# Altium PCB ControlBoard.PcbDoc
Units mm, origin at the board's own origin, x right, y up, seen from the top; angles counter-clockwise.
Board outline 49.91 x 49.78 mm, 2 copper layers (Top Layer, Bottom Layer), stack 0.325 mm thick; 61 components, 68 nets, 312 pads, 113 vias.
Unrouted connection lines stored in the file: 1.
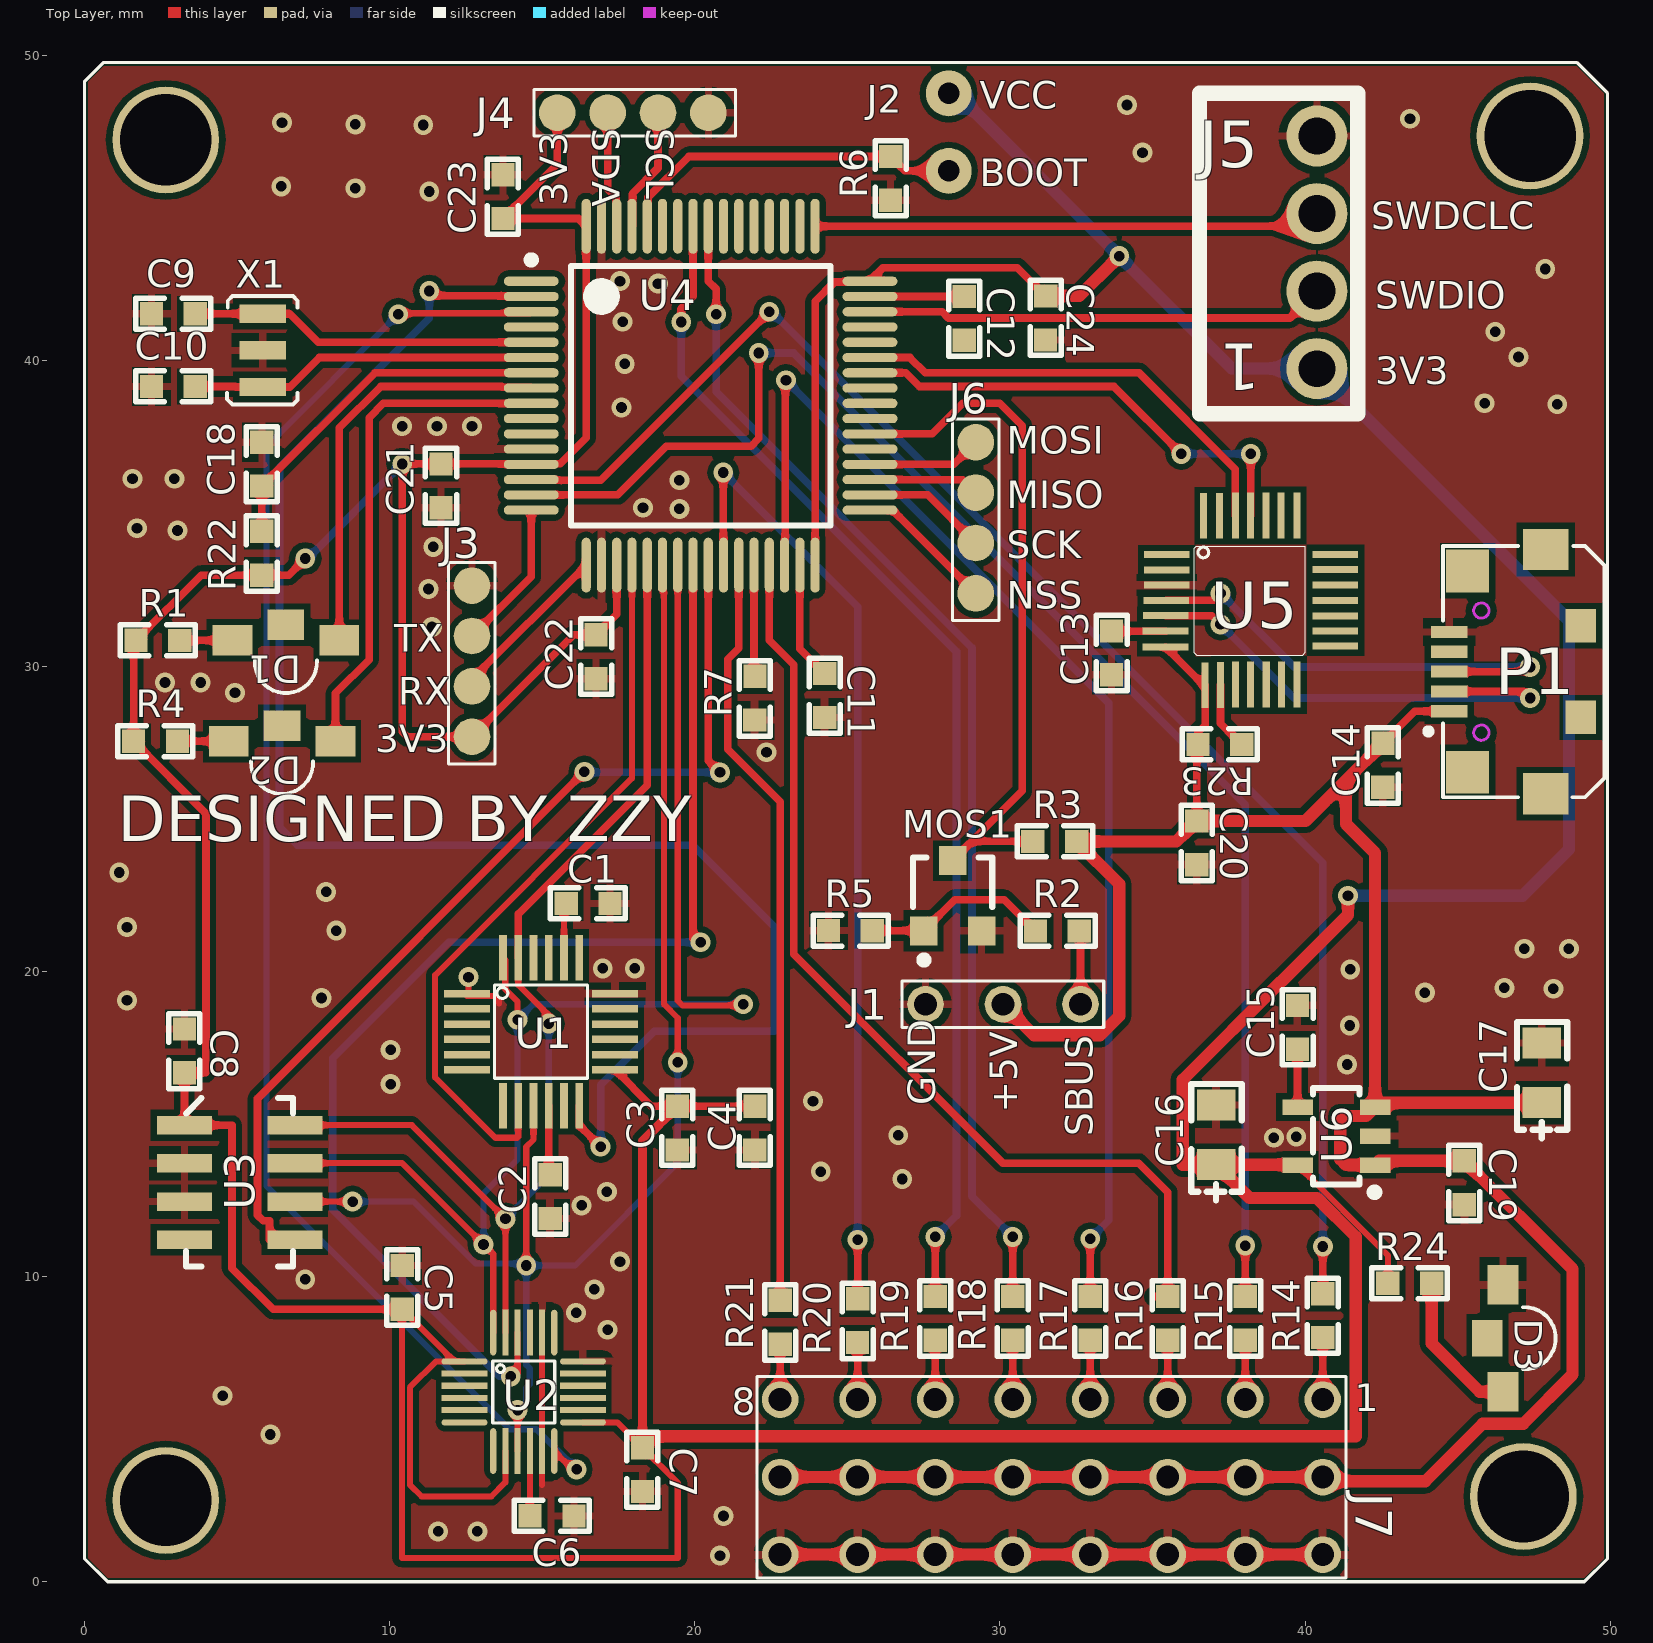
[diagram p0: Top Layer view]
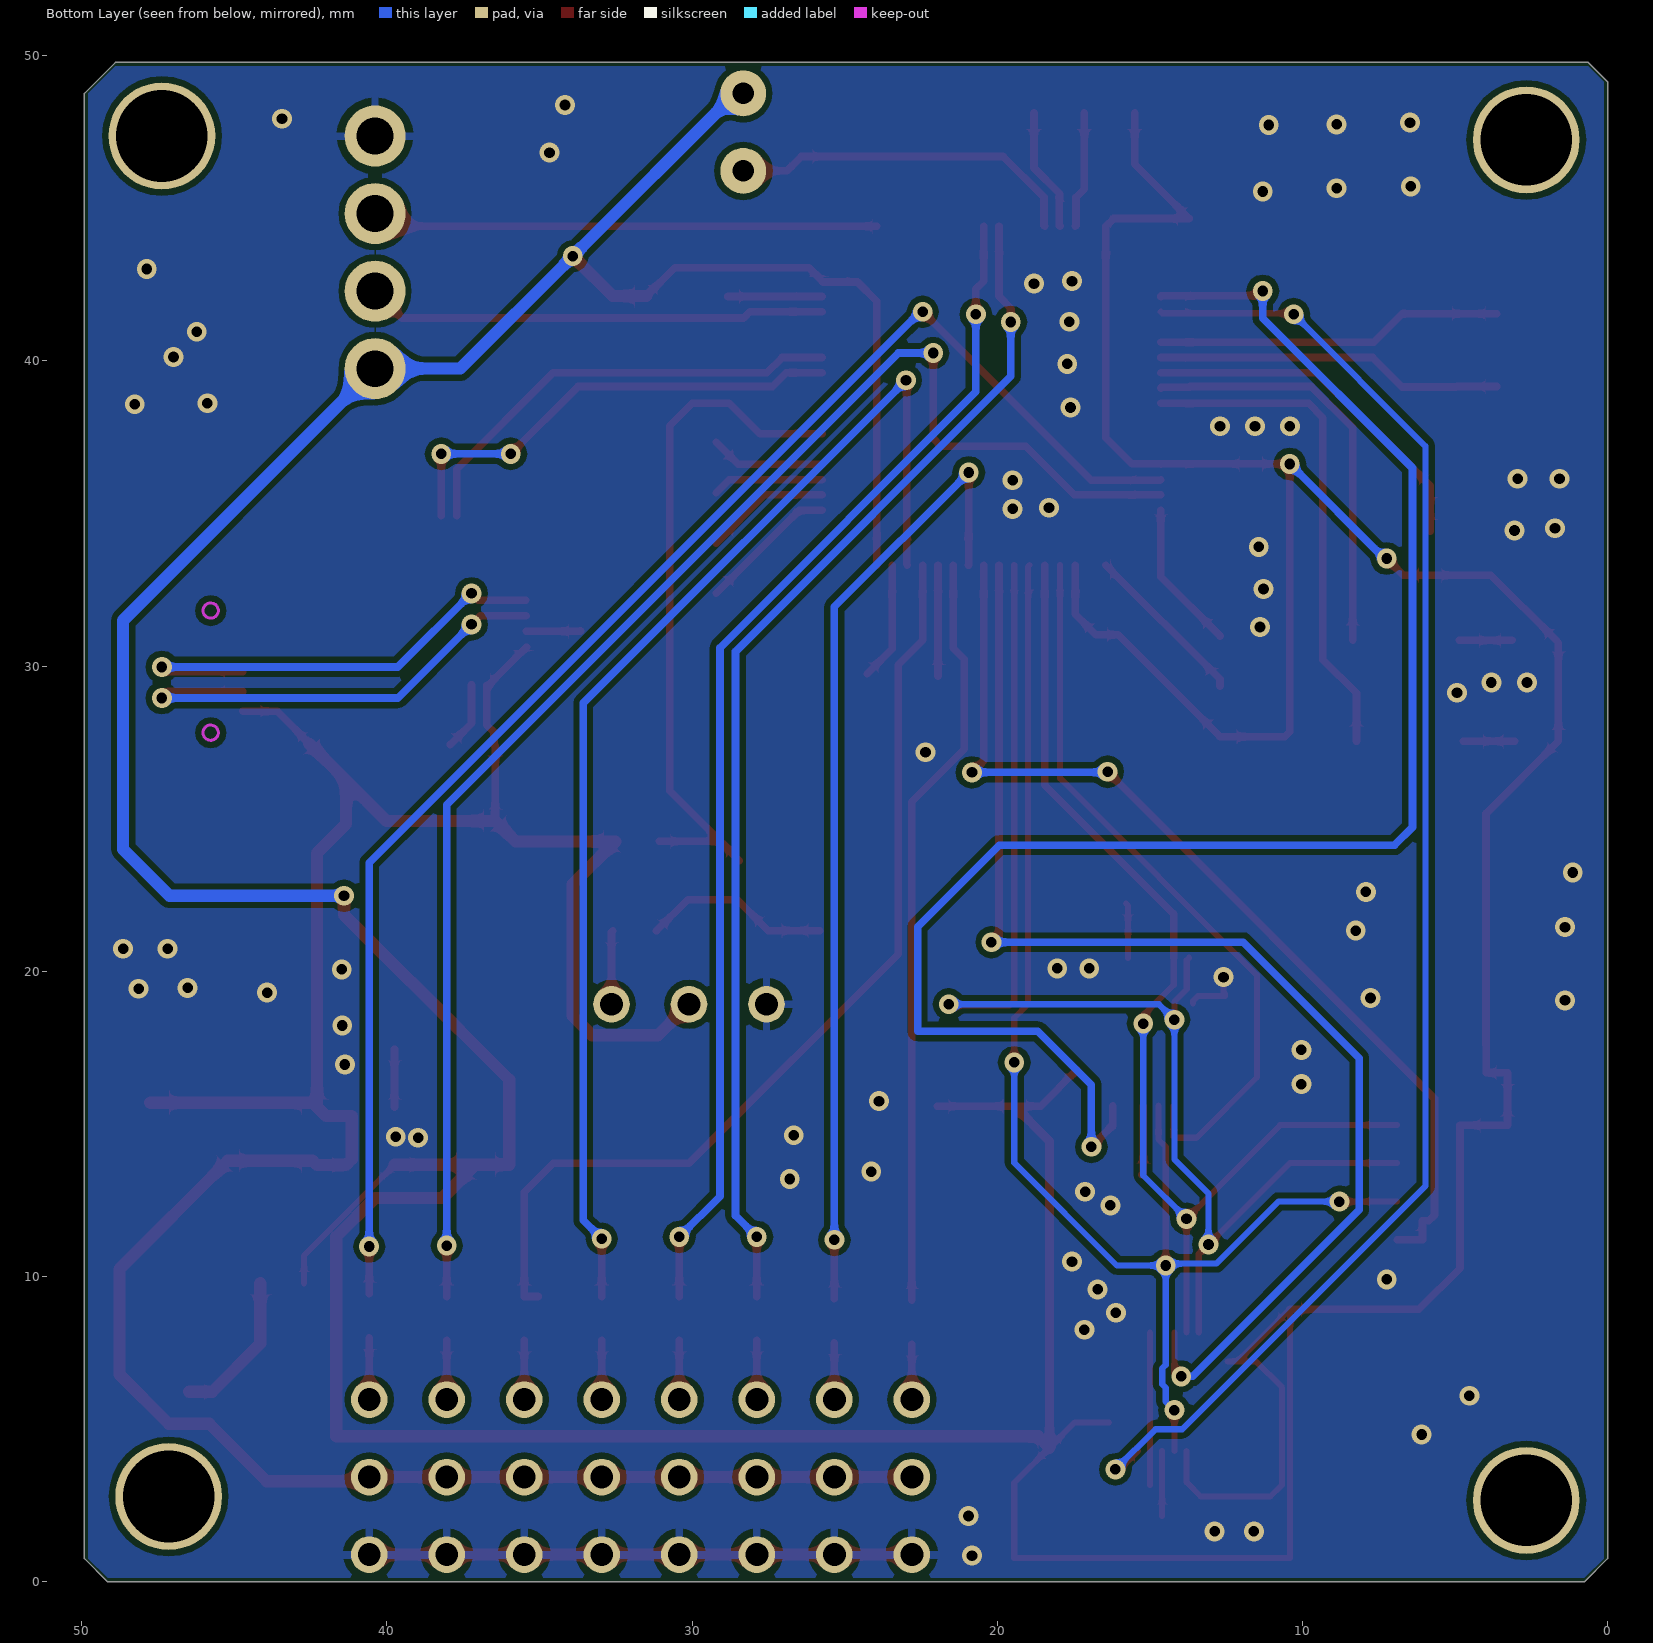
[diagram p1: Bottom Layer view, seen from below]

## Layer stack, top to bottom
Top Solder: solder mask 0.0102, Solder Resist, Dk 3.5
Top Layer: signal copper 0.0356
Dielectric 1: core 0.254, FR-4, Dk 4.2
Bottom Layer: signal copper 0.0356
Bottom Solder: solder mask 0.0102, Solder Resist, Dk 3.5

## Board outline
0,0.762 0,49.149 0.635,49.784 48.895,49.784 49.911,48.768 49.911,0.762 49.149,0 0.762,0

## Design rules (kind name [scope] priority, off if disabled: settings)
Clearance [All] p1: gap=0.2 ignorepadtopadclearanceinfootprint=FALSE except(0: Arc-Hole Track-Hole SMDPad-Hole THPad-Hole Via-Hole Fill-Hole Poly-Hole Region-Hole Text-Hole)
DiffPairsRouting [All] p1: maxlimit=0.254 minlimit=0.2 mostfreqgap=0.254 toplayer_minwidth=0.2 toplayer_maxwidth=0.381 toplayer_prefwidth=0.381 bottomlayer_minwidth=0.2 bottomlayer_maxwidth=0.381 bottomlayer_prefwidth=0.381 maxuncoupledlength=12.7
PolygonConnect [All] p1: connectstyle=Relief reliefconductorwidth=0.254 reliefentries=4 polygonreliefangle="90 Angle" airgapwidth=0.254
RoutingCorners [All] p1: cornerstyle=45-Degree minsetback=1.27 maxsetback=2.54
RoutingVias [All] p1: holewidth=0.35 width=0.65 viastyle="Through Hole" minholewidth=0.3 minwidth=0.6 maxholewidth=2 maxwidth=2
SolderMaskExpansion [All] p1: expansion=0.102
UnRoutedNet [All] p1: checkbadconnections=TRUE
Width [All] p1: maxlimit=2 minlimit=0.2 preferedwidth=0.3 minimp=50.000000 maximp=50.000000 favimp=50.000000
27 further rules are at their usual default settings.

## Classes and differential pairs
component class mcu: C9 C10 C11 C12 C13 C14 C15 C16 C17 C18 C19 C20 C21 C22 C23 C24 D1 D2 D3 J1 J2 J3 J4 J5 J6 J7 MOS1 P1 R1 R2 R3 R4 R5 R6 R7 R14 R15 R16 R17 R18 R19 R20 R21 R22 R23 R24 U4 U5 U6 X1
component class imu: C1 C2 C3 C4 C5 C6 C7 C8 U1 U2 U3

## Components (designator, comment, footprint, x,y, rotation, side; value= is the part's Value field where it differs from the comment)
C1 "0.01uF" 0603P 16.51,22.225 r180 top
C2 "2.2uF" 0603P 15.266,12.611 r90 top
C3 "2.2uF" 0603P 19.429,14.859 r90 top
C4 "0.1uF" 0603P 21.969,14.859 r90 top
C5 "0.1uF" 0603P 10.414,9.652 r270 top
C6 "0.1uF" 0603P 15.329,2.157 r180 top
C7 "0.01uF" 0603P 18.288,3.683 r270 top
C8 "0.1uF" 0603P 3.28,17.399 r270 top
C9 "22pF" 0603P 2.921,41.546 r180 top
C10 "22pF" 0603P 2.921,39.163 r180 top
C11 "2.2uF" 0603P 24.259,29.045 r270 top
C12 "2.2uF" 0603P 28.829,41.401 r270 top
C13 "0.1uF" 0603P 33.657,30.442 r270 top
C14 "0.1uF" 0603P 42.547,26.759 r270 top
C15 "104" 0603P 39.751,18.161 r90 top
C16 "10uF" "C0805 钽电容" 37.082,13.665 r90 top
C17 "100uF" "C0805 钽电容" 47.75,15.697 r90 top
C18 "104" 0603P 5.817,36.627 r270 top
C19 "104" 0603P 45.212,13.081 r270 top
C20 "1uF" 0603P 36.451,24.219 r270 top
C21 "0.1uF" 0603P 11.684,35.903 r90 top
C22 "0.1uF" 0603P 16.764,30.302 r90 top
C23 "0.1uF" 0603P 13.716,45.39 r270 top
C24 "0.1uF" 0603P 31.496,41.402 r90 top
D1 "LED" "LED1206  侧贴" 6.604,30.844 r180 top
D2 "LED" "LED1206  侧贴" 6.477,27.542 r180 top
D3 "LED" "LED1206  侧贴" 46.482,7.978 r270 top
J1 "SBUS" 3P 27.559,18.923 r90 top
J2 "BOOT" X3 28.321,48.768 r0 top
J3 "UART" 4P 12.7,32.639 r0 top
J4 "I2C" 4P 15.494,48.133 r90 top
J5 "SWD" X4 40.386,39.751 r180 top
J6 "SPI" 4P 29.21,37.338 r0 top
J7 "pwm" 3x8P 40.577,3.429 r270 top
MOS1 "SI2302" SO-G3/C2.5 28.448,22.479 r0 top
P1 "MICRO-USB" MICRO_USB5P_SOP 44.722,29.821 r270 top
R1 "510R" 0603P 2.413,30.844 r180 top
R2 "10K" 0603P 31.877,21.325 r0 top
R3 "10K" 0603P 31.788,24.259 r0 top
R4 "510R" 0603P 2.337,27.542 r180 top
R5 "10K" 0603P 25.095,21.336 r0 top
R6 "10K" 0603P 26.416,45.974 r90 top
R7 "10K" 0603P 21.971,28.956 r270 top
R14 "10K" 0603P 40.579,8.725 r270 top
R15 "10K" 0603P 38.037,8.636 r270 top
R16 "10K" 0603P 35.499,8.636 r270 top
R17 "10K" 0603P 32.957,8.636 r270 top
R18 "10K" 0603P 30.417,8.636 r270 top
R19 "10K" 0603P 27.879,8.636 r270 top
R20 "10K" 0603P 25.337,8.56 r270 top
R21 "10K" 0603P 22.799,8.509 r270 top
R22 "100K" 0603P 5.817,33.706 r270 top
R23 "10K" 0603P 37.211,27.432 r180 top
R24 "510R" 0603P 43.434,9.779 r180 top
U1 "mpu6000" MPU6050 14.966,18.022 r0 top
U2 "mpu9250" mpu9250 14.397,6.223 r0 top
U3 "MS5611-01BA" MS5611-01BA 5.08,13.081 r0 top value=10-1200mbar
U4 "STM32F405RGT6" STM-LQFP64_N 20.193,38.862 r0 top
U5 "CP2102" CP2102 38.225,32.155 r270 top
U6 "SP6205EM5-3.3" SOT23-5S 42.291,13.655 r180 top
X1 "8MHz" XTAL3215 5.842,40.346 r90 top

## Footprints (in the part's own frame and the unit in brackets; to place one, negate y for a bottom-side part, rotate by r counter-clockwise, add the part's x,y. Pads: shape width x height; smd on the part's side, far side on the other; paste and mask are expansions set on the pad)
3P [mm]
  round 1.2 hole 0.75: 1(0,0) 2(0,-2.54) 3(0,-5.08)
  silkscreen extent -0.76,-5.84 0.76,0.76
3x8P [mm]
  round 1.2 hole 0.75: 1(2.54,0) 1(2.54,-2.54) 1(2.54,-5.08) 1(2.54,-7.62) 1(2.54,-10.16) 1(2.54,-12.7) 1(2.54,-15.24) 1(2.54,-17.78) 2(0,0) 2(0,-2.54) 2(0,-5.08) 2(0,-7.62) 2(0,-10.16) 2(0,-12.7) 2(0,-15.24) 2(0,-17.78) 3(-2.54,0) 4(-2.54,-2.54) 5(-2.54,-5.08) 6(-2.54,-7.62) 7(-2.54,-10.16) 8(-2.54,-12.7) 9(-2.54,-15.24) 10(-2.54,-17.78)
  silkscreen extent -3.3,-18.54 3.3,0.76
4P [mm]
  round 1.2 smd: 1(0,0) 2(0,-1.651) 3(0,-3.302) 4(0,-4.953)
  silkscreen extent -0.76,-5.84 0.76,0.76
0603P [mil]
  rect 30x30 smd: 1(-28,0) 2(28.5,-0.06)
  silkscreen extent -48,-20 49,20
"C0805 钽电容" [mil]
  rect 40x50 smd: 1(0,-0.06) 2(77,-0.06)
  silkscreen extent -46,-33 104,32
CP2102 [mm]
  rect 0.23x1.5 smd: 1(-1.5,-2.76) 2(-1,-2.76) 3(-0.5,-2.76) 4(0,-2.78) 5(0.5,-2.79) 6(1.01,-2.8) 7(1.53,-2.8) 15(1.5,2.76) 16(1,2.76) 17(0.51,2.76) 18(0,2.76) 19(-0.5,2.76) 20(-1.01,2.76) 21(-1.51,2.76)
  rect 1.5x0.23 smd: 8(2.78,-1.5) 9(2.77,-1) 10(2.76,-0.5) 11(2.76,-0.01) 12(2.76,0.5) 13(2.76,1) 14(2.76,1.51) 22(-2.78,1.5) 23(-2.78,0.99) 24(-2.78,0.49) 25(-2.78,-0.01) 26(-2.78,-0.51) 27(-2.77,-1.03) 28(-2.77,-1.55)
  silkscreen extent -1.77,-1.86 1.79,1.78
"LED1206  侧贴" [mm]
  rect 1.3x1 smd: 1(-1.75,0) 3(1.75,0)
  rect 1.2x1 smd: 2(0,-0.508)
  silkscreen extent -1.02,0.66 1.02,1.72
MICRO_USB5P_SOP [mm]
  rect 1.35x1.5 smd: 0(-4,3.16) 0(4,3.16)
  rect 1.4x1.4 smd: 0(-3.3,0.6) 0(3.3,0.6)
  rect 1.1x1 smd: 0(-1.5,4.3) 0(1.5,4.3)
  rect 0.4x1.2 smd: 1(1.3,0) 2(0.65,0) 3(0,0) 4(-0.65,0) 5(-1.3,0)
  Keep-Out Layer circle w0.1: c2,1.05 r0.25
  Keep-Out Layer circle w0.1: c-2,1.05 r0.25
  silkscreen extent -4.11,-0.79 4.11,5.08
MPU6050 [mm]
  rect 1.5x0.25 smd: 1(-2.425,1.25) 2(-2.425,0.75) 3(-2.425,0.25) 4(-2.425,-0.25) 5(-2.425,-0.75) 6(-2.425,-1.25) 13(2.425,-1.25) 14(2.425,-0.75) 15(2.425,-0.25) 16(2.425,0.25) 17(2.425,0.75) 18(2.425,1.25)
  rect 0.25x1.5 smd: 7(-1.25,-2.425) 8(-0.75,-2.425) 9(-0.25,-2.425) 10(0.25,-2.425) 11(0.75,-2.425) 12(1.25,-2.425) 19(1.25,2.425) 20(0.75,2.425) 21(0.25,2.425) 22(-0.25,2.425) 23(-0.75,2.425) 24(-1.25,2.425)
  silkscreen extent -1.52,-1.52 1.52,1.52
mpu9250 [mm]
  rrect100% 1.5x0.2 smd: 1(-1.94,1) 6(-1.94,-1) 13(1.94,-1) 18(1.94,1)
  rect 1.5x0.2 smd: 2(-1.94,0.6) 3(-1.94,0.2) 4(-1.94,-0.2) 5(-1.94,-0.6) 14(1.94,-0.6) 15(1.94,-0.2) 16(1.94,0.2) 17(1.94,0.6)
  rrect100% 0.2x1.5 smd: 7(-1,-1.94) 12(1,-1.94) 19(1,1.94) 24(-1,1.94)
  rect 0.2x1.5 smd: 8(-0.6,-1.94) 9(-0.2,-1.94) 10(0.2,-1.94) 11(0.6,-1.94) 20(0.6,1.94) 21(0.2,1.94) 22(-0.2,1.94) 23(-0.6,1.94)
  silkscreen extent -1.02,-1.02 1.02,1.02
MS5611-01BA [mm] "MS5611-01BA"
  rect 1.8x0.61 smd: 1(-1.8,1.88) 2(-1.8,0.635) 3(-1.8,-0.625) 4(-1.8,-1.875) 5(1.818,-1.875) 6(1.818,-0.625) 7(1.818,0.635) 8(1.818,1.88)
  silkscreen extent -1.75,-2.75 1.75,2.77, body extent -1.51,-2.49 1.49,2.51, height 1
SO-G3/C2.5 [mm]
  rect 0.9x0.95 smd: 1(-0.95,-1.148) 2(0.95,-1.148) 3(0,1.148)
  silkscreen extent -1.3,-2.23 1.3,1.25
SOT23-5S [mm]
  rect 1x0.508 smd: 1(0,0) 2(0,-0.95) 3(0,-1.9) 4(2.54,-1.9) 5(2.54,0)
  silkscreen extent 0,-2.52 2.03,0.89
STM-LQFP64_N [mm] "Thin QFP, 64-Leads, Body 10x10mm, Pitch 0.5mm, IPC Medium Density"
  oval 1.8x0.3 smd: 1(-5.55,3.75) 2(-5.55,3.25) 3(-5.55,2.75) 4(-5.55,2.25) 5(-5.55,1.75) 6(-5.55,1.25) 7(-5.55,0.75) 8(-5.55,0.25) 9(-5.55,-0.25) 10(-5.55,-0.75) 11(-5.55,-1.25) 12(-5.55,-1.75) 13(-5.55,-2.25) 14(-5.55,-2.75) 15(-5.55,-3.25) 16(-5.55,-3.75) 33(5.55,-3.75) 34(5.55,-3.25) 35(5.55,-2.75) 36(5.55,-2.25) 37(5.55,-1.75) 38(5.55,-1.25) 39(5.55,-0.75) 40(5.55,-0.25) 41(5.55,0.25) 42(5.55,0.75) 43(5.55,1.25) 44(5.55,1.75) 45(5.55,2.25) 46(5.55,2.75) 47(5.55,3.25) 48(5.55,3.75)
  oval 0.3x1.8 smd: 17(-3.75,-5.55) 18(-3.25,-5.55) 19(-2.75,-5.55) 20(-2.25,-5.55) 21(-1.75,-5.55) 22(-1.25,-5.55) 23(-0.75,-5.55) 24(-0.25,-5.55) 25(0.25,-5.55) 26(0.75,-5.55) 27(1.25,-5.55) 28(1.75,-5.55) 29(2.25,-5.55) 30(2.75,-5.55) 31(3.25,-5.55) 32(3.75,-5.55) 49(3.75,5.55) 50(3.25,5.55) 51(2.75,5.55) 52(2.25,5.55) 53(1.75,5.55) 54(1.25,5.55) 55(0.75,5.55) 56(0.25,5.55) 57(-0.25,5.55) 58(-0.75,5.55) 59(-1.25,5.55) 60(-1.75,5.55) 61(-2.25,5.55) 62(-2.75,5.55) 63(-3.25,5.55) 64(-3.75,5.55)
  silkscreen extent -5.67,-4.25 4.25,4.57, body extent -5,-5 5,5, height 1.6
X3 [mm]
  round 1.5 hole 0.7: 1(0,0) 2(0,-2.54)
X4 [mm]
  round 2 hole 1.2: 1(0,0) 2(0,-2.54) 3(0,-5.08) 4(0,-7.62)
  silkscreen extent -1.34,-9.02 3.85,1.48
XTAL3215 [mm]
  rect 0.6x1.524 smd: 1(-1.2,0) 2(0,0) 3(1.2,0)
  silkscreen extent -1.78,-1.14 1.78,1.17

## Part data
C1 C2 C3 C4 C5 C6 C7 C8 C9 C10 C11 C12 C13 C14 C15 C18 C19 C20 C21 C22 C23 C24: library part C
C16 C17: library part CAP
D1 D2 D3: library part "LED 1206 侧贴  单色", "LED 1206 侧贴  单色"
MOS1: library part MOS-N, "AP2306"
P1: library part USB5
R1 R2 R3 R4 R5 R6 R7 R14 R15 R16 R17 R18 R19 R20 R21 R22 R23 R24: library part R
U3: "Board Mount Pressure Sensors", 3DR_PARTNO=ECM0835
U4: "ARM Cortex-M4 32-bit MCU+FPU, 210 DMIPS, 1024 kB Flash, 192 kB Internal RAM, 51 I/Os, 64-pin LQFP, -40 to 85 degC, Tray", I/Os (High Current)=51, Manufacturer=STMicroelectronics, Operating Frequency(F) (Processor speed) (MHz)=168, Supplier Part Number 1=497-11767-ND, Supply Voltage(Vcc) max (V)=3.6, Supply Voltage(Vcc) min (V)=1.8
U6: library part SP6205
X1: library part XTAL-3215

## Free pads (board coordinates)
  round 3.5 hole 3: 2(2.667,47.244) 3(47.148,2.794) 4(47.371,47.371) 5(2.667,2.667)

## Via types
v1: diameter 0.65, hole 0.35, Top Layer to Bottom Layer, 113 vias

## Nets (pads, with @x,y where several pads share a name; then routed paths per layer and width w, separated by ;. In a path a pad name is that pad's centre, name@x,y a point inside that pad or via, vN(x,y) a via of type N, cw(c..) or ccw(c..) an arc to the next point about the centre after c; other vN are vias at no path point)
BOOT0: J2.2 R6.2 U4.60 | length 11.6
  Top Layer w0.25: U4.60 18.468,44.437 18.468,45.359 19.807,46.698 R6.2 26.888,46.228 J2.2
GND: C1.1 C2.1 C3.1 C4.1 C5.1 C6.1 C7.2 C8.1 C9.2 C10.2 C11.2 C12.2 C13.2 C14.2 C15.2 C16.2 C17.2 C18.1 C19.2 C20.2 C21.1 C22.1 C23.1 C24.1 D3.1 J1.1 J3.1 J4.4 J5.4 J7.1 MOS1.2 P1.5 R5.1 R6.1 R7.2 U1.1 U1.18 U2.11 U2.18 U2.20 U3.2 U3.3 U4.12 U4.18 U4.63 U5.3 U6.2 X1.2 | length 24.6
  Top Layer w0.2: v1(12.586,19.812) 12.586,19.317 U1.1 12.541,19.197 13.415,19.197 13.591,19.021 13.591,18.954 ; 14.997,3.177 U2.11 U2.20
  Top Layer w0.4: J7.1@22.797,0.889 25.337,0.889 27.877,0.889 30.417,0.889 32.957,0.889 35.497,0.889 38.037,0.889 J7.1@40.577,0.889
  other v1: 20.828,0.857 11.59,1.651 12.876,1.651 20.943,2.157 6.096,4.826 4.53,6.096 17.145,8.255 16.113,8.813 16.711,9.582 7.239,9.908 17.548,10.49 16.294,12.334 17.12,12.779 26.797,13.194 24.13,13.438 38.975,14.547 39.709,14.579 26.67,14.63 23.876,15.748 10.035,16.306 41.375,16.947 10.035,17.427 41.46,18.224 1.397,19.05 7.773,19.128 43.922,19.304 48.133,19.431 46.527,19.458 41.48,20.066 16.987,20.099 18.034,20.099 47.182,20.741 48.641,20.741 8.255,21.336 1.397,21.45 7.921,22.606 1.143,23.241 22.352,27.178 4.938,29.128 2.645,29.464 3.81,29.464 11.389,31.284 11.275,32.528 11.43,33.909 3.051,34.443 1.722,34.517 19.495,35.154 18.306,35.192 19.495,36.09 1.578,36.139 2.949,36.139 10.412,37.863 11.557,37.863 12.7,37.863 17.597,38.475 48.26,38.582 45.88,38.612 17.704,39.905 46.989,40.132 46.228,40.957 17.637,41.285 18.796,42.534 17.548,42.616 47.866,43.014 11.303,45.55 8.88,45.66 6.452,45.72 34.671,46.826 11.105,47.73 8.88,47.752 6.477,47.81 43.434,47.938 34.163,48.387
I2C1_SCL: J4.3 U4.61 | length 4.1
  Top Layer w0.25: U4.61 17.968,44.437 17.968,45.495 18.796,46.323 J4.3
I2C1_SDA: J4.2 U4.62 | length 3.8
  Top Layer w0.25: J4.2 17.145,45.632 17.418,45.359 17.418,44.437 U4.62
IMU_CS1: U1.8 U4.20 | length 24
  Top Layer w0.2: U1.8 14.216,14.581 14.182,14.547 13.467,14.547 11.491,16.523 11.491,19.873 17.943,26.325 U4.20
IMU_CS2: U2.22 U4.24 | length 40.8
  Top Layer w0.2: v1(13.97,6.731) 14.197,6.958 U2.22
  Top Layer w0.25: U4.24 19.943,21.078 v1@20.193,20.828
  Bottom Layer w0.25: v1(13.97,6.731) 13.597,6.731 8.141,12.187 8.141,17.158 11.938,20.955 v1(20.193,20.955)
IMU_CS3: U3.5 U4.25 | length 32.3
  Top Layer w0.25: U3.5 6.066,11.206 6.066,11.826 5.863,11.826 5.673,12.017 5.673,15.833 v1(16.383,26.543) ; U4.25 20.443,26.906 v1(20.828,26.521)
  Bottom Layer w0.25: v1(16.383,26.543) 16.405,26.521 v1(20.828,26.521)
IMU_INT1: U1.12 U4.2 | length 54.1
  Top Layer w0.25: v1(11.303,42.291) 11.457,42.137 14.618,42.137 U4.2 ; U1.12 16.216,14.951 v1(16.916,14.251)
  Bottom Layer w0.25: v1(11.303,42.291) 11.303,41.402 6.394,36.493 6.394,24.721 6.985,24.13 19.939,24.13 22.606,21.463 22.606,18.034 18.669,18.034 16.916,16.281 v1(16.916,14.251)
IMU_INT2: U2.12 U4.3 | length 49.7
  Top Layer w0.2: v1(10.287,41.529) 10.32,41.562 14.593,41.562 U4.3 ; U2.12 15.997,3.683 v1(16.129,3.683)
  Bottom Layer w0.2: v1(10.287,41.529) 5.969,37.211 5.969,12.967 13.938,4.998 14.814,4.998 v1(16.129,3.683)
IMU_SPI1_MISO: U1.9 U2.9 U3.6 U4.22 | length 46.2
  Top Layer w0.2: U3.6 v1(8.791,12.456) ; U2.9 v1(14.197,5.623) ; v1(14.478,10.363) 14.478,14.251 14.716,14.489 U1.9 ; U4.22 18.993,33.262 18.993,18.922 19.443,18.472 v1(19.443,17.018)
  Bottom Layer w0.2: v1(8.791,12.456) 10.79,12.456 12.822,10.424 14.417,10.424 v1(14.478,10.363) ; v1(14.197,5.623) 14.478,5.904 14.478,6.355 14.595,6.472 14.595,6.99 14.478,7.107 v1(14.478,10.363) ; v1(19.443,17.018) 19.443,13.728 16.078,10.363 v1(14.478,10.363)
IMU_SPI1_MOSI: U1.24 U2.24 U3.7 U4.23 | length 44.5
  Top Layer w0.2: U3.7 10.414,13.716 v1(13.081,11.049) 13.397,10.733 U2.24 ; U1.24 13.791,20.372 13.791,19.417 14.197,19.011 v1(14.197,18.415) ; U4.23 19.443,19.038 19.596,18.885 21.59,18.885 v1(21.59,18.923)
  Bottom Layer w0.2: v1(13.081,11.049) 13.081,12.727 14.197,13.843 v1(14.197,18.415) 14.705,18.923 v1(21.59,18.923)
IMU_SPI1_SCK: U1.23 U2.23 U3.8 U4.21 | length 36.1
  Top Layer w0.2: U3.8 10.728,14.961 v1(13.797,11.892) U2.23 ; U1.23 14.216,19.558 15.216,18.558 v1(15.216,18.288)
  Top Layer w0.25: U1.23 14.216,21.878 18.443,26.105 U4.21
  Bottom Layer w0.2: v1(13.797,11.892) 15.216,13.311 v1(15.216,18.288)
LED1: D1.1 U4.8 | length 13.8
  Top Layer w0.25: D1.1 8.354,37.806 9.71,39.162 13.671,39.162 13.671,39.137 14.618,39.137 U4.8
LED2: D2.1 U4.9 | length 16.6
  Top Layer w0.25: D2.1 8.227,29.107 9.329,30.209 9.329,38.144 9.797,38.612 U4.9
M3V3: C3.2 C4.2 C5.2 C7.1 C8.2 C16.1 C21.2 C22.2 C23.2 C24.2 J2.1 J3.4 J4.1 J5.1 R1.2 R4.2 R22.2 R24.2 U1.13 U2.1 U2.8 U2.13 U3.1 U4.13 U4.19 U4.32 U4.48 U4.64 U6.5 | length 251.4
  Top Layer w0.2: U2.1 U2.1@12.117,7.223 ; U2.8 13.797,3.256 13.335,2.794 11.047,2.794 10.668,3.173 10.668,6.367 11.524,7.223 U2.1@12.117,7.223 ; U2.13 17.459,5.223 C7.1 19.443,3.239 19.443,0.774 10.402,0.774 10.402,8.918 C5.2 U2.1@12.117,7.223 ; U6.5 42.71,10.696 R24.2
  Top Layer w0.25: v1(7.239,33.528) 6.693,32.982 R22.2 3.825,32.982 R1.2 1.613,30.769 R4.2 3.986,25.171 3.986,17.595 3.975,17.584 3.975,16.675 C8.2 3.28,16.673 U3.1 4.836,14.961 4.836,10.277 6.185,8.928 C5.2 ; J4.1 15.494,46.446 C23.2 16.189,44.666 U4.64 16.443,37.49 15.59,36.637 14.668,36.637 U4.13 14.628,36.627 C21.2 v1(10.414,36.627) 10.414,27.846 10.574,27.686 J3.4 16.04,31.026 C22.2 17.443,31.703 U4.19 ; U1.13 18.58,15.583 C3.2 C4.2 ; U4.32 23.943,41.951 24.579,42.587 25.718,42.587 U4.48 25.743,42.634 26.162,43.053 30.571,43.053 C24.2
  Top Layer w0.3: C7.1 18.288,14.44 C3.2
  Top Layer w0.4: C7.1 18.659,4.765 41.656,4.765 41.656,11.303 40.386,12.573 38.176,12.573 C16.1 ; C24.2 32.601,42.126 v1@33.782,43.307 ; U6.5 39.741,13.665 C16.1 ; v1(41.402,22.479) 41.402,21.844 39.224,19.666 39.206,19.666 35.992,16.452 35.992,13.665 C16.1
  Bottom Layer w0.25: v1(7.239,33.528) 7.315,33.528 v1(10.414,36.627)
  Bottom Layer w0.4: J2.1 28.575,48.768 v1(33.909,43.434) 37.592,39.751 J5.1 48.641,31.496 48.641,24.003 47.117,22.479 v1(41.402,22.479)
MCU_RX: U4.43 U5.26 | length 15
  Top Layer w0.25: U4.43 27.051,40.112 27.551,39.612 34.556,39.612 37.715,36.453 U5.26
MCU_TX: U4.42 U5.25 | length 15.6
  Top Layer w0.25: U4.42 26.915,39.612 27.365,39.162 33.736,39.162 v1(35.941,36.957) ; U5.25 v1(38.215,36.957)
  Bottom Layer w0.25: v1(35.941,36.957) v1(38.215,36.957)
NetC1_2: C1.2 U1.20 | length 1.8
  Top Layer w0.2: U1.20 15.716,22.157 C1.2
NetC2_2: C2.2 U1.10 | length 2.3
  Top Layer w0.25: U1.10 15.216,13.387 C2.2
NetC6_2: C6.2 U2.10 | length 2.1
  Top Layer w0.2: U2.10 14.597,2.167 C6.2
NetC9_1: C9.1 U4.5 X1.3 | length 11.4
  Top Layer w0.25: C9.1 X1.3 6.729,41.546 7.663,40.612 U4.5
NetC10_1: C10.1 U4.6 X1.1 | length 11.4
  Top Layer w0.25: C10.1 4.938,39.163 4.955,39.146 X1.1 6.729,39.146 7.695,40.112 U4.6
NetC11_1: C11.1 U4.31 | length 3.9
  Top Layer w0.25: U4.31 23.443,30.572 C11.1
NetC12_1: C12.1 U4.47 | length 3.1
  Top Layer w0.25: U4.47@25.757,42.126 U4.47 C12.1
NetC13_1: C13.1 U5.6 | length 1.8
  Top Layer w0.25: C13.1 33.665,31.145 U5.6
NetC15_1: C15.1 U6.4 | length 1.9
  Top Layer w0.25: U6.4 C15.1
NetD1_3: D1.3 R1.1 | length 1.7
  Top Layer w0.25: R1.1 D1.3
NetD2_3: D2.3 R4.1 | length 1.7
  Top Layer w0.25: R4.1 D2.3
NetD3_3: D3.3 R24.1 | length 5
  Top Layer w0.4: R24.1 44.145,7.803 45.72,6.228 D3.3
NetJ7_3: J7.3 R14.2 | length 2
  Top Layer w0.25: J7.3 R14.2
NetJ7_4: J7.4 R15.2 | length 1.9
  Top Layer w0.25: R15.2 38.037,7.91 J7.4
NetJ7_5: J7.5 R16.2 | length 1.9
  Top Layer w0.25: J7.5 R16.2
NetJ7_6: J7.6 R17.2 | length 1.9
  Top Layer w0.25: R17.2 32.957,7.91 J7.6
NetJ7_7: J7.7 R18.2 | length 1.9
  Top Layer w0.25: R18.2 30.417,7.91 J7.7
NetJ7_8: J7.8 R19.2 | length 1.9
  Top Layer w0.25: J7.8 R19.2
NetJ7_9: J7.9 R20.2 | length 1.9
  Top Layer w0.25: R20.2 25.337,7.834 J7.9
NetJ7_10: J7.10 R21.2 | length 1.8
  Top Layer w0.25: J7.10 R21.2
NetMOS1_1: MOS1.1 R2.1 R5.2 | length 6.2
  Top Layer w0.25: R5.2 27.494,21.334 MOS1.1 28.519,22.352 30.139,22.352 R2.1
NetP1_2: P1.2 U5.5 | length 15.8
  Top Layer w0.25: U5.5 36.939,31.655 v1(37.225,31.369) ; P1.2 47.156,29.171 v1(47.371,28.956)
  Bottom Layer w0.25: v1(37.225,31.369) 39.638,28.956 v1(47.371,28.956)
NetP1_3: P1.3 U5.4 | length 15.7
  Top Layer w0.25: U5.4 36.995,32.155 v1(37.225,32.385) ; P1.3 47.22,29.821 v1(47.371,29.972)
  Bottom Layer w0.25: v1(37.225,32.385) 39.638,29.972 v1(47.371,29.972)
NetR7_1: R7.1 U4.28 | length 3.6
  Top Layer w0.25: R7.1@21.943,29.667 U4.28
NetR23_1: R23.1 U5.9 | length 2.2
  Top Layer w0.25: U5.9 37.225,28.129 R23.1
RST: C18.2 R22.1 U4.7 | length 11.9
  Top Layer w0.25: R22.1 5.815,34.419 C18.2 9.524,39.612 U4.7
SBUS: J1.3 R2.2 | length 2.4
  Top Layer w0.25: R2.2 32.639,21.285 J1.3
SBUS_UART6_RX: MOS1.3 R3.1 U4.38 | length 22.9
  Top Layer w0.25: U4.38 27.785,37.612 28.785,38.612 29.998,38.612 30.734,37.876 30.734,25.913 29.079,24.259 ; MOS1.3 29.079,24.259 ; R3.1 29.079,24.259
SDIO_CK: U4.53
SDIO_CMD: U4.54
SDIO_D0: U4.39
SDIO_D1: U4.40
SDIO_D2: U4.51
SDIO_D3: U4.52
SPI2_MISO: J6.2 U4.35 | length 3.6
  Top Layer w0.25: U4.35 28.785,36.112 J6.2
SPI2_MOSI: J6.1 U4.36 | length 3.8
  Top Layer w0.25: U4.36 28.484,36.612 J6.1
SPI2_NSS: J6.4 U4.33 | length 4.6
  Top Layer w0.25: U4.33 26.483,35.112 J6.4
SPI2_SCK: J6.3 U4.34 | length 4.1
  Top Layer w0.25: U4.34 27.634,35.612 J6.3
SWDCLK: J5.3 U4.49 | length 16.6
  Top Layer w0.25: U4.49 39.967,44.412 J5.3
SWDIO: J5.2 U4.46 | length 15.1
  Top Layer w0.25: U4.46 28.107,41.612 28.313,41.406 39.501,41.406 J5.2
TIM2_CH1: R14.1 U4.14 | length 49.8
  Top Layer w0.25: U4.14 14.668,36.087 16.918,36.087 v1(22.443,41.612) ; R14.1 v1(40.579,10.983)
  Bottom Layer w0.25: v1(22.443,41.612) 22.524,41.612 40.579,23.557 v1(40.579,10.983)
TIM2_CH2: R15.1 U4.15 | length 49.2
  Top Layer w0.25: U4.15 17.47,35.612 19.069,37.211 21.844,37.211 22.098,37.465 v1(22.098,40.259) ; R15.1 v1(38.037,11.015)
  Bottom Layer w0.25: v1(22.098,40.259) 23.241,40.259 38.037,25.463 v1(38.037,11.015)
TIM2_CH3: R16.1 U4.29 | length 32.4
  Top Layer w0.25: U4.29 22.443,30.853 23.249,30.047 23.249,20.566 30.099,13.716 34.544,13.716 35.499,12.761 R16.1 35.041,9.347
TIM2_CH4: R17.1 U4.30 | length 40.7
  Top Layer w0.25: U4.30 22.968,33.337 22.968,39.351 v1(22.987,39.37) ; R17.1 v1(32.957,11.239)
  Bottom Layer w0.25: v1(22.987,39.37) 33.564,28.793 33.564,11.845 v1(32.957,11.239)
TIM3_CH1: R18.1 U4.56 | length 39.2
  Top Layer w0.25: U4.56 20.443,42.616 20.701,42.358 v1(20.701,41.529) ; R18.1 v1(30.417,11.301)
  Bottom Layer w0.25: v1(20.701,41.529) 20.701,38.99 29.083,30.608 29.083,12.636 v1(30.417,11.301)
TIM3_CH2: R19.1 U4.57 | length 39.2
  Top Layer w0.25: v1(19.558,41.275) 19.558,41.731 19.943,42.116 U4.57 ; R19.1 v1(27.879,11.301)
  Bottom Layer w0.25: v1(19.558,41.275) 19.558,39.497 28.575,30.48 28.575,11.997 v1(27.879,11.301)
TIM3_CH3: R20.1 U4.26 | length 31.9
  Top Layer w0.25: v1(20.933,36.344) 20.933,33.322 U4.26 ; R20.1 v1(25.337,11.204)
  Bottom Layer w0.25: v1(20.933,36.344) 25.337,31.94 v1(25.337,11.204)
TIM3_CH4: R21.1 U4.27 | length 25
  Top Layer w0.25: U4.27 21.443,30.587 21.082,30.226 21.082,27.275 22.799,25.558 R21.1
UART2_RX: J3.3 U4.17 | length 5.5
  Top Layer w0.25: J3.3 12.7,29.569 U4.17
UART2_TX: J3.2 U4.16 | length 4.9
  Top Layer w0.25: J3.2 14.643,32.931 U4.16
VBUS: C14.1 C17.1 C19.1 C20.1 J1.2 J7.2 P1.1 R3.2 R23.2 U5.7 U5.8 U6.1 U6.3 | length 90.7
  Top Layer w0.25: U5.7 36.675,29.375 U5.8 36.725,28.067 36.487,27.829 R23.2 36.451,27.397 C20.1 ; C14.1 43.598,28.521 P1.1
  Top Layer w0.4: J7.2@22.797,3.429 25.337,3.429 27.877,3.429 30.417,3.429 32.957,3.429 35.497,3.429 38.037,3.429 40.577,3.429 40.577,3.296 43.934,3.296 45.816,5.178 47.148,5.178 48.761,6.791 48.761,10.244 C19.1 42.428,13.792 U6.1 41.336,13.655 41.148,13.843 41.148,15.259 41.995,15.259 U6.3 ; J1.2 31.115,17.907 33.274,17.907 33.909,18.542 33.909,22.86 R3.2 35.778,24.257 C20.1 40.007,24.93 41.336,26.259 ; C14.1 41.336,26.259 ; C17.1 42.433,15.697 U6.3 ; 41.336,26.259 41.336,24.831 42.291,23.876 U6.3
pads on no net: D1.2 D2.2 D3.2 P1.0 P1.4 U1.2 U1.3 U1.4 U1.5 U1.6 U1.7 U1.11 U1.14 U1.15 U1.16 U1.17 U1.19 U1.21 U1.22 U2.2 U2.3 U2.4 U2.5 U2.6 U2.7 U2.14 U2.15 U2.16 U2.17 U2.19 U2.21 U3.4 U4.1 U4.4 U4.10 U4.11 U4.37 U4.41 U4.44 U4.45 U4.50 U4.55 U4.58 U4.59 U5.1 U5.2 U5.10 U5.11 U5.12 U5.13 U5.14 U5.15 U5.16 U5.17 U5.18 U5.19 U5.20 U5.21 U5.22 U5.23 U5.24 U5.27 U5.28

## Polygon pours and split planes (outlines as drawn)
no net on Top Overlay (solid): 0.127,49.022
GND on Bottom Layer (solid, pour order 18): 0.635,49.657 48.895,49.657 49.784,48.768 49.784,0.762 49.149,0.127 0.762,0.127 0.127,0.762 0.127,49.149
GND on Top Layer (solid, pour order 16): 0.635,49.657 48.895,49.657 49.784,48.768 49.784,0.762 49.149,0.127 0.762,0.127 0.762,0.139 0.127,0.774 0.127,49.149

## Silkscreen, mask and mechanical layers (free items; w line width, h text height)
Top Overlay:
  the board outline again, w0.1
  text "SDA" at 16.637,47.625 h0.9 r270
  text "SCL" at 18.415,47.625 h0.9 r270
  text "3V3" at 15.824,45.085 h0.9 r90
  text "SWDCLC" at 42.164,44.323 h0.9
  text "SWDIO" at 42.291,41.707 h0.9
  text "3V3" at 42.291,39.243 h0.9
  text "MOSI" at 30.226,36.957 h0.9
  text "MISO" at 30.226,35.179 h0.9
  text "SCK" at 30.226,33.528 h0.9
  text "NSS" at 30.226,31.877 h0.9
  text "TX" at 10.16,30.48 h0.9
  text "RX" at 10.287,28.74 h0.9
  text "3V3" at 9.525,27.178 h0.9
  text "DESIGNED BY ZZY" at 1.092,24.257 h1.5
  text "GND" at 27.877,15.621 h0.9 r90
  text "+5V" at 30.569,15.367 h0.9 r90
  text "SBUS" at 33.033,14.605 h0.9 r90
  text "1" at 41.62,5.588 h0.9
  text "8" at 21.209,5.461 h0.9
